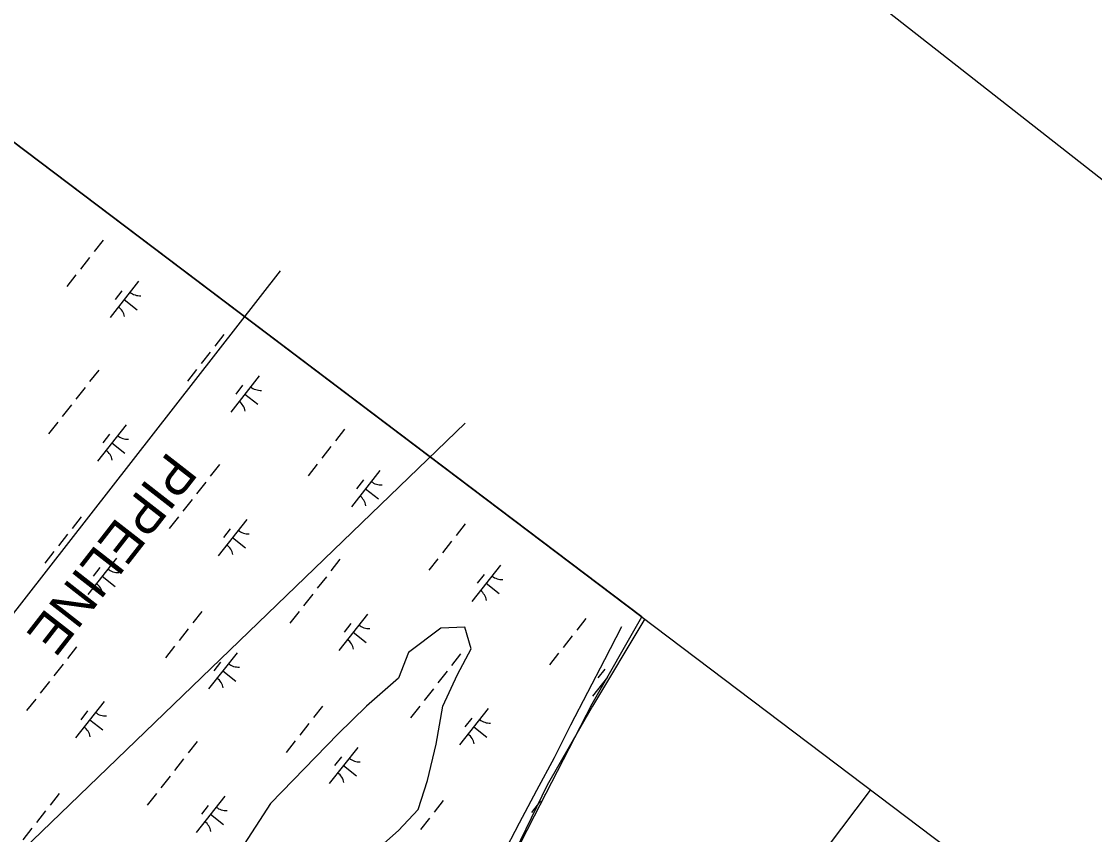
# Model space of a CAD drawing. Extents: x 3896831 to 3918110, y 171006 to 193349.
# Drawn here: x 3911189 to 3912353, y 187534 to 188416 of the extents above; entities that cross this region are included whole.
import ezdxf

# ---------------------------------------------------------------- set-up
doc = ezdxf.new("R2010")
doc.units = 0
for name, color, linetype in [('V-ANNO-SYMB', 7, 'Continuous'), ('V-GRID-FRAM', 7, 'Continuous'), ('V-RIVR-EDGE', 7, 'Continuous'), ('V-RRAP-FSHR', 7, 'Continuous'), ('V-TOPO-MINR', 7, 'Continuous'), ('V-TOPO-SHOR', 7, 'Continuous'), ('V-UTIL-IDEN', 7, 'Continuous'), ('V-UTIL-LINE', 7, 'Continuous'), ('V-WETL-SWMP', 7, 'Continuous')]:
    doc.layers.add(name, color=color, linetype=linetype)

msp = doc.modelspace()

# ---------------------------------------------------------------- linework, layer by layer
at = {"layer": 'V-ANNO-SYMB'}
msp.add_lwpolyline([(3907767.9, 191844.4), (3897563.8, 178825.1), (3906582.3, 171756.8), (3916786.3, 184776.1), (3907767.9, 191844.4)], dxfattribs=at)
at = {"layer": 'V-GRID-FRAM'}
msp.add_lwpolyline([(3916044.9, 184610), (3906752.8, 172754.1), (3900055.1, 177809.8), (3909313.3, 189695.8), (3916044.9, 184610)], dxfattribs=at)
at = {"layer": 'V-RIVR-EDGE'}
msp.add_lwpolyline([(3911865.2, 187767.9), (3911808.6, 187673.2), (3911759.3, 187587.7), (3911695.2, 187455.7)], dxfattribs=at)
at = {"layer": 'V-RRAP-FSHR'}
msp.add_lwpolyline([(3911839.9, 187759.2), (3911821.4, 187723.7), (3911803, 187688.2), (3911784.6, 187652.7), (3911766.8, 187617.3), (3911747.6, 187581.8), (3911729.1, 187546.3), (3911710.6, 187510.8)], dxfattribs=at)
at = {"layer": 'V-TOPO-MINR'}
msp.add_lwpolyline([(3912110.3, 187582.7), (3912109.9, 187582.2), (3912063, 187520.2), (3912016.3, 187458.1), (3911806, 187176.9), (3911786.7, 187150.5), (3911767.7, 187123.9), (3911749.1, 187097), (3911730.8, 187069.9), (3911675.8, 186986.6), (3911384.6, 186512.1), (3911369.5, 186491.3), (3911368.2, 186489.6), (3911365.6, 186486.1), (3911364.3, 186484.4), (3911362.3, 186481.8), (3911361, 186480), (3910921.7, 185915.3), (3910911.1, 185901.5), (3910900.5, 185887.7), (3910890, 185873.8), (3910879.6, 185859.8), (3910869.3, 185845.7), (3910859.2, 185831.5)], dxfattribs=at)
at = {"layer": 'V-TOPO-SHOR'}
msp.add_lwpolyline([(3911563.2, 187507.9), (3911597.9, 187538.3), (3911619.3, 187561.1), (3911629.6, 187592.6), (3911639, 187632.1), (3911646.1, 187673.3), (3911662.1, 187707.5), (3911676.9, 187735.5), (3911670, 187758.9), (3911643.9, 187757.8), (3911608.8, 187731.3), (3911598, 187703.8), (3911563.3, 187673.3), (3911532.7, 187643.4), (3911459.1, 187567.9), (3911426.8, 187517.6)], dxfattribs=at)
at = {"layer": 'V-UTIL-LINE'}
for points in [[(3907581.4, 183502.3), (3907734.6, 183396.3), (3908170.6, 183973.7), (3908524.1, 184327.2), (3908913, 184727.9), (3909396.1, 185399.6), (3909514, 185670.6), (3909808.6, 186000.6), (3910067.8, 186295.2), (3911010.5, 187556.1), (3911470.1, 188145.3)], [(3911670.5, 187980.3), (3909726.1, 186106.6), (3909690.7, 186047.7), (3909490.4, 185423.1), (3908571.2, 184256.5), (3908123.4, 183643.7), (3907157.1, 182394.6), (3906544.4, 181593.3), (3906120.1, 181051.2), (3905460.2, 180002.4), (3904670.7, 178765.1), (3903951.9, 177622.1), (3903445.2, 176832.5), (3902962, 176054.8), (3902856, 175866.2)]]:
    msp.add_lwpolyline(points, dxfattribs=at)
at = {"layer": 'V-WETL-SWMP'}
for p, q in [((3911862.1, 187770.2), (3911016.1, 188409.3)), ((3911277.7, 188178.8), (3911267.8, 188166.2)), ((3911262.9, 188159.9), (3911253, 188147.3)), ((3911248.1, 188141), (3911238.2, 188128.4)), ((3911315.9, 188134), (3911285.1, 188094.6)), ((3911298.1, 188123.8), (3911290.7, 188114.3)), ((3911300.5, 188114.3), (3911314.7, 188103.2)), ((3911408.6, 188076.2), (3911398.8, 188063.6)), ((3911393.8, 188057.3), (3911383.9, 188044.7)), ((3911272.8, 188037.8), (3911262.9, 188025.2)), ((3911379, 188038.4), (3911369.1, 188025.8)), ((3911446.8, 188031.4), (3911416, 187992)), ((3911429, 188021.2), (3911421.6, 188011.7)), ((3911258, 188018.9), (3911248.1, 188006.3)), ((3911431.4, 188011.7), (3911445.6, 188000.6)), ((3911243.2, 188000), (3911233.3, 187987.4)), ((3911228.4, 187981.1), (3911218.5, 187968.5)), ((3911302.5, 187978.4), (3911271.6, 187939.1)), ((3911284.7, 187968.2), (3911277.3, 187958.8)), ((3911539.5, 187973.6), (3911529.7, 187961)), ((3911287.1, 187958.7), (3911301.2, 187947.6)), ((3911524.7, 187954.7), (3911514.9, 187942.1)), ((3911403.7, 187935.2), (3911393.8, 187922.6)), ((3911509.9, 187935.8), (3911500.1, 187923.2)), ((3911577.7, 187928.8), (3911546.9, 187889.4)), ((3911388.9, 187916.3), (3911379, 187903.7)), ((3911560, 187918.6), (3911552.5, 187909.1)), ((3911562.3, 187909.1), (3911576.5, 187898)), ((3911374.1, 187897.4), (3911364.2, 187884.8)), ((3911253.8, 187878.7), (3911243.9, 187866.1)), ((3911359.3, 187878.5), (3911349.4, 187865.9)), ((3911433.4, 187875.8), (3911402.6, 187836.4)), ((3911670.5, 187871), (3911660.6, 187858.4)), ((3911239, 187859.8), (3911229.1, 187847.2)), ((3911415.6, 187865.6), (3911408.2, 187856.2)), ((3911418, 187856.1), (3911432.2, 187845)), ((3911655.7, 187852.1), (3911645.8, 187839.5)), ((3911224.2, 187840.9), (3911214.3, 187828.3)), ((3911292, 187833.8), (3911261.2, 187794.5)), ((3911274.2, 187823.7), (3911266.8, 187814.2)), ((3911534.6, 187832.6), (3911524.7, 187820)), ((3911640.8, 187833.2), (3911631, 187820.6)), ((3911708.7, 187826.1), (3911677.8, 187786.8)), ((3911276.6, 187814.2), (3911290.8, 187803.1)), ((3911519.8, 187813.7), (3911509.9, 187801.1)), ((3911690.9, 187816), (3911683.5, 187806.5)), ((3911693.2, 187806.5), (3911707.4, 187795.4)), ((3911505, 187794.8), (3911495.1, 187782.2)), ((3911384.7, 187776.1), (3911374.9, 187763.5)), ((3911490.2, 187775.9), (3911480.3, 187763.3)), ((3911564.3, 187773.2), (3911533.5, 187733.8)), ((3911801.4, 187768.4), (3911791.5, 187755.8)), ((3911808.3, 187675.7), (3911862.1, 187770.2)), ((3911369.9, 187757.2), (3911360.1, 187744.6)), ((3911546.5, 187763), (3911539.1, 187753.5)), ((3911548.9, 187753.5), (3911563.1, 187742.4)), ((3911786.6, 187749.5), (3911776.7, 187736.9)), ((3911248.9, 187737.7), (3911239, 187725.1)), ((3911355.1, 187738.3), (3911345.3, 187725.7)), ((3911422.9, 187731.2), (3911392.1, 187691.9)), ((3911665.5, 187730), (3911655.7, 187717.4)), ((3911665.5, 187730), (3911655.7, 187717.4)), ((3911771.8, 187730.6), (3911761.9, 187718)), ((3911234.1, 187718.8), (3911224.2, 187706.2)), ((3911405.1, 187721), (3911397.7, 187711.6)), ((3911407.5, 187711.6), (3911421.7, 187700.5)), ((3911650.7, 187711.1), (3911640.9, 187698.5)), ((3911650.7, 187711.1), (3911640.9, 187698.5)), ((3911821.8, 187713.3), (3911814.4, 187703.9)), ((3911219.3, 187699.9), (3911209.4, 187687.3)), ((3911824.7, 187704.6), (3911808.7, 187684.2)), ((3911824.2, 187703.9), (3911824.3, 187703.8)), ((3911635.9, 187692.2), (3911626, 187679.6)), ((3911635.9, 187692.2), (3911626, 187679.6)), ((3911204.5, 187681), (3911194.6, 187668.4)), ((3911278.6, 187678.3), (3911247.8, 187638.9)), ((3911515.7, 187673.4), (3911505.8, 187660.9)), ((3911621.1, 187673.3), (3911611.2, 187660.7)), ((3911621.1, 187673.3), (3911611.2, 187660.7)), ((3911745.5, 187554.3), (3911808.3, 187675.7)), ((3911260.8, 187668.1), (3911253.4, 187658.6)), ((3911695.2, 187670.6), (3911664.4, 187631.2)), ((3911677.5, 187660.4), (3911670.1, 187650.9)), ((3911263.2, 187658.6), (3911277.4, 187647.5)), ((3911500.8, 187654.6), (3911491, 187642)), ((3911679.8, 187650.9), (3911694, 187639.8)), ((3911379.8, 187635.1), (3911369.9, 187622.5)), ((3911486, 187635.7), (3911476.2, 187623.1)), ((3911553.9, 187628.6), (3911523, 187589.3)), ((3911553.9, 187628.6), (3911523, 187589.3)), ((3911365, 187616.2), (3911355.1, 187603.6)), ((3911536.1, 187618.4), (3911528.7, 187609)), ((3911536.1, 187618.4), (3911528.7, 187609)), ((3911538.4, 187609), (3911552.6, 187597.8)), ((3911538.4, 187609), (3911552.6, 187597.8)), ((3911350.2, 187597.3), (3911340.3, 187584.7)), ((3911229.9, 187578.5), (3911220.1, 187565.9)), ((3911335.4, 187578.4), (3911325.5, 187565.8)), ((3911409.5, 187575.7), (3911378.7, 187536.3)), ((3911646.6, 187570.8), (3911636.7, 187558.2)), ((3911752, 187570.7), (3911742.2, 187558.1)), ((3911757.7, 187577.9), (3911757, 187577)), ((3911215.1, 187559.6), (3911205.3, 187547.1)), ((3911391.7, 187565.5), (3911384.3, 187556)), ((3911394.1, 187556), (3911408.3, 187544.9)), ((3911631.8, 187551.9), (3911621.9, 187539.4)), ((3911679.6, 187424.8), (3911745.5, 187554.3)), ((3911200.3, 187540.8), (3911190.4, 187528.2))]:
    msp.add_line(p, q, dxfattribs=at)
msp.add_lwpolyline([(3911563.2, 187507.9), (3911597.9, 187538.3), (3911619.3, 187561.1), (3911629.6, 187592.6), (3911639, 187632.1), (3911646.1, 187673.3), (3911662.1, 187707.5), (3911676.9, 187735.5), (3911670, 187758.9), (3911643.9, 187757.8), (3911608.8, 187731.3), (3911598, 187703.8), (3911563.3, 187673.3), (3911532.7, 187643.4), (3911459.1, 187567.9), (3911426.8, 187517.6)], dxfattribs=at)
for centre, start, end in [((3911317.7, 188135.9), 231.1403, 272.6839), ((3911283.6, 188092.4), 11.1403, 52.6839), ((3911448.6, 188033.3), 231.1403, 272.6839), ((3911414.6, 187989.8), 11.1403, 52.6839), ((3911304.3, 187980.3), 231.1403, 272.6839), ((3911270.2, 187936.8), 11.1403, 52.6839), ((3911579.5, 187930.7), 231.1403, 272.6839), ((3911545.5, 187887.2), 11.1403, 52.6839), ((3911435.2, 187877.7), 231.1403, 272.6839), ((3911401.1, 187834.2), 11.1403, 52.6839), ((3911293.8, 187835.8), 231.1403, 272.6839), ((3911710.5, 187828.1), 231.1403, 272.6839), ((3911259.7, 187792.3), 11.1403, 52.6839), ((3911676.4, 187784.6), 11.1403, 52.6839), ((3911566.1, 187775.1), 231.1403, 272.6839), ((3911532.1, 187731.6), 11.1403, 52.6839), ((3911424.7, 187733.2), 231.1403, 272.6839), ((3911390.7, 187689.7), 11.1403, 52.6839), ((3911807.3, 187682), 47.3842, 52.6839), ((3911280.4, 187680.2), 231.1403, 272.6839), ((3911246.3, 187636.7), 11.1403, 52.6839), ((3911697.1, 187672.5), 231.1403, 272.6839), ((3911663, 187629), 11.1403, 52.6839), ((3911555.7, 187630.5), 231.1403, 272.6839), ((3911555.7, 187630.5), 231.1403, 272.6839), ((3911521.6, 187587.1), 11.1403, 52.6839), ((3911521.6, 187587.1), 11.1403, 52.6839), ((3911411.3, 187577.6), 231.1403, 272.6839), ((3911377.3, 187534.1), 11.1403, 52.6839)]:
    msp.add_arc(centre, 17.6, start, end, dxfattribs=at)

# ---------------------------------------------------------------- texts
at = {"layer": 'V-UTIL-IDEN'}
msp.add_text('PIPELINE', height=42, rotation=232.0843, dxfattribs=at).set_placement((3911348.6, 187950.9))

doc.saveas('drawing.dxf')
